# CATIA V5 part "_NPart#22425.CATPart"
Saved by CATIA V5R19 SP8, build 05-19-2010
Part number: Pièce25
Revision: ANY
Definition: UNKNOWN
Nomenclature: Pièce25
Source: Unknown
Bounding box of the stored display mesh (mm): x 69 to 97, y 4 to 14, z -2.5 to 13.5
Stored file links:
  D:\Documents\1_Travail\1 - ac-limoges.fr\ac-limoges.fr\Emmanuel Maynard - STI2D_Turgot\2 -2I2D\2_SEQUENCE_Serrure_Biométrique\5-Spé_ITEC\Serrure_Bio_Eleve\_NPart#22425.CATPart
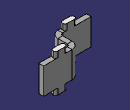
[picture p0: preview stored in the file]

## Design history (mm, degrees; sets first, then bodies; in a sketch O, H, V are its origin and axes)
Body1 "Extrusion4" (main body)
  Solid1: solid without history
